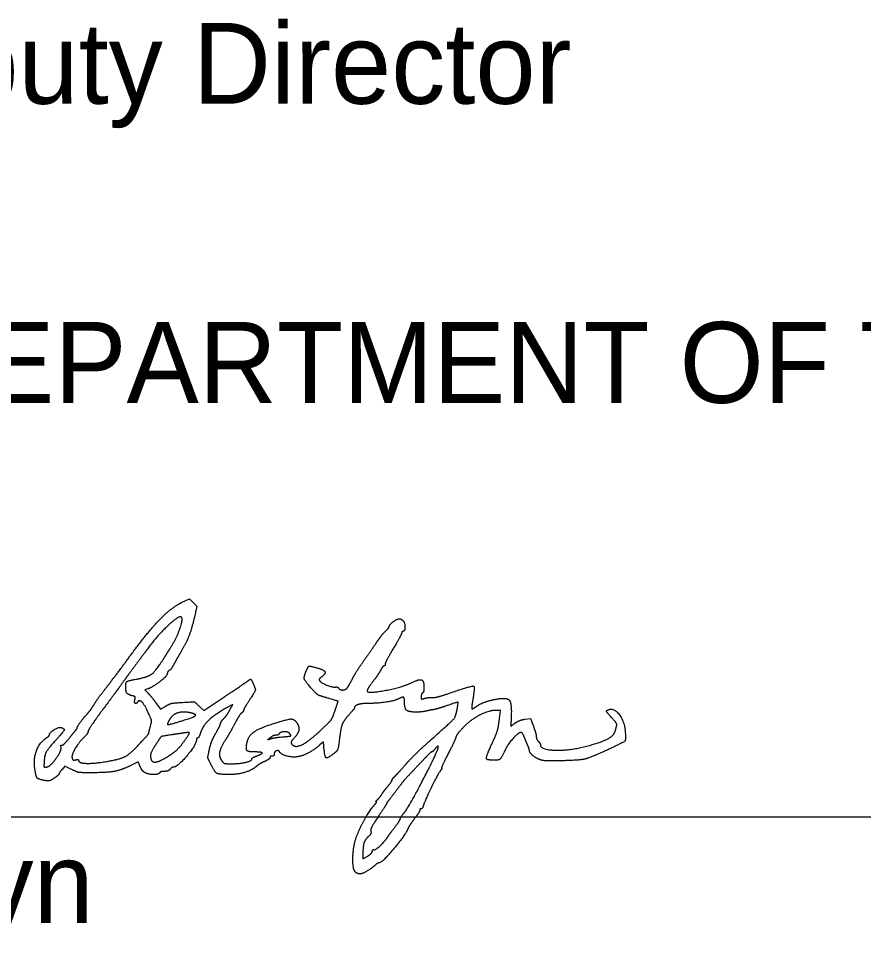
# Model space of a CAD drawing. Extents: x -7.5 to 26.5, y 3.5 to 25.5.
# Drawn here: x 18.323 to 19.785, y 10.747 to 12.355 of the extents above; entities that cross this region are included whole.
import ezdxf

# ---------------------------------------------------------------- set-up
doc = ezdxf.new("R2010")
doc.units = 0
doc.layers.add('SH_Data', color=7, linetype='Continuous')
doc.layers.add('SH_Text', color=7, linetype='Continuous')

msp = doc.modelspace()

# ---------------------------------------------------------------- linework, layer by layer
at = {"layer": 'SH_Data'}
msp.add_line((17.0432, 10.9729), (20.5432, 10.9729), dxfattribs=at)
at = {"layer": 'SH_Text'}
for points in [[(18.6062, 11.3442), (18.6188, 11.35), (18.6252, 11.3436), (18.6316, 11.3373), (18.6272, 11.3186)], [(18.5463, 11.1942), (18.5413, 11.1926), (18.5464, 11.1875)], [(18.6353, 11.1645), (18.6434, 11.1569), (18.6796, 11.181)], [(18.5601, 11.1708), (18.5687, 11.1593), (18.5775, 11.1645)], [(18.6891, 11.1592), (18.6936, 11.1672), (18.6881, 11.1642)], [(19.155, 11.1433), (19.1565, 11.1571), (19.1487, 11.1571)], [(19.1988, 11.1417), (19.2085, 11.1432), (19.2136, 11.1297)], [(18.8509, 11.0955), (18.8503, 11.1024), (18.8444, 11.0972)], [(18.5333, 11.0599), (18.5299, 11.068), (18.5161, 11.0611)], [(18.4146, 11.0549), (18.4031, 11.0607), (18.3981, 11.0549)], [(18.9187, 10.9094), (18.9187, 10.9), (18.9262, 10.9044)]]:
    msp.add_lwpolyline(points, dxfattribs=at)
for points in [[(18.5167, 11.2523), (18.5463, 11.2929), (18.5881, 11.3358), (18.6062, 11.3442)], [(18.6048, 11.3184), (18.6011, 11.322), (18.5626, 11.2863), (18.5472, 11.265)], [(18.5865, 11.2663), (18.5959, 11.2812), (18.6079, 11.3153), (18.6048, 11.3184)], [(18.6272, 11.3186), (18.6222, 11.2974), (18.613, 11.2738), (18.6036, 11.2579)], [(18.9643, 11.3022), (18.9643, 11.3051), (18.9775, 11.3154), (18.9812, 11.3154)], [(18.9812, 11.3154), (18.9832, 11.3155), (18.9862, 11.3142), (18.9878, 11.3126)], [(18.9878, 11.3126), (18.9913, 11.3092), (18.9916, 11.2939), (18.9883, 11.2939)], [(18.9439, 11.2769), (18.9478, 11.2828), (18.954, 11.2905), (18.9577, 11.2941)], [(18.9577, 11.2941), (18.9613, 11.2978), (18.9643, 11.3014), (18.9643, 11.3022)], [(18.9859, 11.2914), (18.9859, 11.29), (18.9794, 11.2779), (18.9715, 11.2645)], [(18.9883, 11.2939), (18.9869, 11.2939), (18.9859, 11.2928), (18.9859, 11.2914)], [(18.9223, 11.2459), (18.9302, 11.2571), (18.9399, 11.2711), (18.9439, 11.2769)], [(18.5472, 11.265), (18.5436, 11.26), (18.5342, 11.2474), (18.5263, 11.2369)], [(18.5759, 11.2496), (18.5792, 11.2548), (18.584, 11.2623), (18.5865, 11.2663)], [(18.6036, 11.2579), (18.6001, 11.252), (18.5949, 11.2428), (18.592, 11.2375)], [(18.9715, 11.2645), (18.9635, 11.2511), (18.9571, 11.2388), (18.9571, 11.237)], [(18.4765, 11.1988), (18.4854, 11.2102), (18.5035, 11.2342), (18.5167, 11.2523)], [(18.5261, 11.211), (18.5467, 11.2147), (18.5608, 11.2256), (18.5759, 11.2496)], [(18.9009, 11.2123), (18.9047, 11.2196), (18.9143, 11.2347), (18.9223, 11.2459)], [(18.5263, 11.2369), (18.5183, 11.2264), (18.5102, 11.2154), (18.5083, 11.2124)], [(18.5835, 11.226), (18.5817, 11.2249), (18.5803, 11.2225), (18.5803, 11.2206)], [(18.592, 11.2375), (18.5892, 11.2322), (18.5854, 11.227), (18.5835, 11.226)], [(18.83, 11.1947), (18.8185, 11.2078), (18.8162, 11.2146), (18.8202, 11.2242)], [(18.8202, 11.2242), (18.8239, 11.2332), (18.8271, 11.2342), (18.8398, 11.2305)], [(18.8398, 11.2305), (18.8518, 11.2269), (18.8546, 11.2207), (18.847, 11.2149)], [(18.9498, 11.2273), (18.948, 11.2237), (18.9419, 11.2146), (18.9362, 11.2071)], [(18.9551, 11.2339), (18.954, 11.2339), (18.9516, 11.2309), (18.9498, 11.2273)], [(18.9571, 11.237), (18.9571, 11.2353), (18.9562, 11.2339), (18.9551, 11.2339)], [(18.5083, 11.2124), (18.5063, 11.2095), (18.4909, 11.1885), (18.4741, 11.1659)], [(18.5083, 11.1989), (18.5083, 11.2057), (18.5124, 11.2085), (18.5261, 11.211)], [(18.5803, 11.2206), (18.5803, 11.2168), (18.5545, 11.1968), (18.5463, 11.1942)], [(18.6796, 11.181), (18.6996, 11.1942), (18.7172, 11.2062), (18.7188, 11.2075)], [(18.7188, 11.2075), (18.7233, 11.2113), (18.7257, 11.2104), (18.7287, 11.2038)], [(18.847, 11.2149), (18.8442, 11.2128), (18.8428, 11.21), (18.8437, 11.2086)], [(18.8437, 11.2086), (18.8464, 11.2049), (18.8663, 11.1967), (18.8709, 11.1974)], [(18.8916, 11.1961), (18.8929, 11.1978), (18.8971, 11.205), (18.9009, 11.2123)], [(18.9362, 11.2071), (18.9305, 11.1996), (18.9259, 11.1924), (18.9259, 11.191)], [(19.0034, 11.2053), (19.0164, 11.2115), (19.0243, 11.2083), (19.0243, 11.1969)], [(18.455, 11.1695), (18.4579, 11.1743), (18.4676, 11.1875), (18.4765, 11.1988)], [(18.5192, 11.1825), (18.5121, 11.1843), (18.5083, 11.19), (18.5083, 11.1989)], [(18.7287, 11.2038), (18.7331, 11.1942), (18.7321, 11.1901), (18.7219, 11.1742)], [(18.8535, 11.1796), (18.8427, 11.1827), (18.8378, 11.1859), (18.83, 11.1947)], [(18.8709, 11.1974), (18.8732, 11.1978), (18.8757, 11.197), (18.8766, 11.1956)], [(18.8766, 11.1956), (18.8787, 11.1921), (18.8888, 11.1925), (18.8916, 11.1961)], [(18.9259, 11.191), (18.9259, 11.1858), (18.9855, 11.1967), (19.0034, 11.2053)], [(19.0243, 11.1969), (19.0243, 11.1923), (19.0232, 11.1879), (19.0219, 11.1871)], [(19.0666, 11.1862), (19.107, 11.2001), (19.1129, 11.1984), (19.1087, 11.1746)], [(18.5243, 11.1762), (18.5253, 11.1798), (18.524, 11.1813), (18.5192, 11.1825)], [(18.5286, 11.1714), (18.5262, 11.1675), (18.523, 11.1711), (18.5243, 11.1762)], [(18.5464, 11.1875), (18.5493, 11.1846), (18.5554, 11.1771), (18.5601, 11.1708)], [(18.8702, 11.1558), (18.8759, 11.1727), (18.8755, 11.1732), (18.8535, 11.1796)], [(18.9792, 11.1765), (18.9736, 11.1735), (18.9435, 11.1691), (18.9285, 11.1691)], [(18.9907, 11.1718), (18.9907, 11.1791), (18.987, 11.1806), (18.9792, 11.1765)], [(19.0219, 11.1871), (19.0205, 11.1863), (19.0195, 11.1835), (19.0195, 11.1808)], [(19.0195, 11.1808), (19.0195, 11.1769), (19.0205, 11.1763), (19.0249, 11.1777)], [(19.0249, 11.1777), (19.0278, 11.1787), (19.0337, 11.1793), (19.0378, 11.1792)], [(19.0378, 11.1792), (19.042, 11.179), (19.0549, 11.1822), (19.0666, 11.1862)], [(19.1147, 11.1637), (19.122, 11.1688), (19.1402, 11.1751), (19.1539, 11.1772)], [(19.1539, 11.1772), (19.1685, 11.1795), (19.1762, 11.1691), (19.1754, 11.1479)], [(18.4387, 11.1476), (18.4452, 11.1549), (18.4495, 11.1606), (18.455, 11.1695)], [(18.4741, 11.1659), (18.4573, 11.1432), (18.4435, 11.1231), (18.4435, 11.1211)], [(18.5474, 11.1528), (18.5413, 11.1665), (18.5315, 11.1762), (18.5286, 11.1714)], [(18.5775, 11.1645), (18.584, 11.1684), (18.5915, 11.17), (18.6067, 11.1709)], [(18.6067, 11.1709), (18.627, 11.1721), (18.6272, 11.1721), (18.6353, 11.1645)], [(18.6881, 11.1642), (18.6647, 11.1517), (18.6419, 11.131), (18.6378, 11.1185)], [(18.6764, 11.1411), (18.6818, 11.1471), (18.6843, 11.1506), (18.6891, 11.1592)], [(18.7219, 11.1742), (18.7166, 11.166), (18.7123, 11.1584), (18.7123, 11.1573)], [(18.9043, 11.1619), (18.9043, 11.161), (18.9001, 11.1556), (18.8949, 11.1499)], [(18.9285, 11.1691), (18.917, 11.1691), (18.9043, 11.1653), (18.9043, 11.1619)], [(19.01, 11.1541), (18.9976, 11.1542), (18.9907, 11.1605), (18.9907, 11.1718)], [(19.037, 11.1066), (19.0725, 11.1381), (19.0794, 11.1463), (19.0819, 11.1596)], [(19.0612, 11.1642), (19.0534, 11.1615), (19.0438, 11.1588), (19.0399, 11.1581)], [(19.0819, 11.1596), (19.084, 11.1711), (19.0822, 11.1715), (19.0612, 11.1642)], [(19.1087, 11.1746), (19.1074, 11.1669), (19.1067, 11.1603), (19.1072, 11.1598)], [(19.1072, 11.1598), (19.1076, 11.1594), (19.111, 11.1611), (19.1147, 11.1637)], [(19.3455, 11.1485), (19.3402, 11.1542), (19.3399, 11.1568), (19.3445, 11.1586)], [(19.3445, 11.1586), (19.3531, 11.1619), (19.3716, 11.137), (19.3726, 11.1207)], [(18.4243, 11.1271), (18.4243, 11.1287), (18.4334, 11.1417), (18.4387, 11.1476)], [(18.5507, 11.1283), (18.5533, 11.1381), (18.553, 11.1403), (18.5474, 11.1528)], [(18.5859, 11.1437), (18.5789, 11.133), (18.5834, 11.1321), (18.6079, 11.1397)], [(18.6185, 11.1532), (18.6076, 11.1554), (18.5902, 11.1503), (18.5859, 11.1437)], [(18.6079, 11.1397), (18.6271, 11.1456), (18.6311, 11.1507), (18.6185, 11.1532)], [(18.7018, 11.1431), (18.6937, 11.1276), (18.6859, 11.1139), (18.6798, 11.1042)], [(18.7087, 11.1524), (18.7068, 11.1507), (18.7037, 11.1465), (18.7018, 11.1431)], [(18.7123, 11.1573), (18.7123, 11.1562), (18.7107, 11.154), (18.7087, 11.1524)], [(18.8519, 11.1285), (18.8624, 11.1386), (18.8665, 11.1447), (18.8702, 11.1558)], [(18.8949, 11.1499), (18.8864, 11.1404), (18.8807, 11.1279), (18.8791, 11.1151)], [(19.0267, 11.1555), (19.0234, 11.1548), (19.0159, 11.1541), (19.01, 11.1541)], [(19.0399, 11.1581), (19.0359, 11.1575), (19.03, 11.1563), (19.0267, 11.1555)], [(19.1487, 11.1571), (19.136, 11.1571), (19.1022, 11.1387), (19.09, 11.1251)], [(19.1403, 11.0955), (19.1494, 11.1154), (19.1534, 11.1285), (19.155, 11.1433)], [(19.1754, 11.1479), (19.1747, 11.1295), (19.1746, 11.1297), (19.1823, 11.1353)], [(19.3546, 11.1194), (19.3585, 11.1312), (19.357, 11.1361), (19.3455, 11.1485)], [(18.3763, 11.1151), (18.3763, 11.1188), (18.3931, 11.1288), (18.3969, 11.1274)], [(18.3969, 11.1274), (18.4028, 11.1251), (18.4006, 11.1202), (18.3862, 11.1043)], [(18.4219, 11.1228), (18.4232, 11.1244), (18.4243, 11.1263), (18.4243, 11.1271)], [(18.5311, 11.0978), (18.5471, 11.1154), (18.5475, 11.1159), (18.5507, 11.1283)], [(18.6639, 11.117), (18.6683, 11.1246), (18.6721, 11.1323), (18.6724, 11.1341)], [(18.6724, 11.1341), (18.6726, 11.1358), (18.6744, 11.139), (18.6764, 11.1411)], [(18.718, 11.1003), (18.7201, 11.1116), (18.7363, 11.1249), (18.7556, 11.1314)], [(18.7556, 11.1314), (18.7875, 11.142), (18.8009, 11.1424), (18.806, 11.1329)], [(18.7949, 11.0997), (18.8003, 11.091), (18.827, 11.1045), (18.8519, 11.1285)], [(18.806, 11.1329), (18.8092, 11.1269), (18.8058, 11.1155), (18.7984, 11.1076)], [(19.1823, 11.1353), (19.1861, 11.1379), (19.1935, 11.1408), (19.1988, 11.1417)], [(19.2136, 11.1297), (19.2164, 11.1222), (19.2187, 11.1141), (19.2187, 11.1116)], [(18.3716, 11.1098), (18.3742, 11.1114), (18.3763, 11.1138), (18.3763, 11.1151)], [(18.4097, 11.1079), (18.4151, 11.1145), (18.4205, 11.1212), (18.4219, 11.1228)], [(18.4361, 11.1104), (18.4262, 11.1007), (18.4139, 11.0786), (18.4157, 11.074)], [(18.4435, 11.1211), (18.4434, 11.1191), (18.4401, 11.1143), (18.4361, 11.1104)], [(18.5887, 11.1149), (18.5709, 11.1123), (18.5688, 11.1112), (18.5616, 11.0999)], [(18.6061, 11.1175), (18.6004, 11.1166), (18.5926, 11.1155), (18.5887, 11.1149)], [(18.611, 11.1059), (18.6189, 11.1172), (18.6179, 11.1194), (18.6061, 11.1175)], [(18.6378, 11.1185), (18.6361, 11.1134), (18.6338, 11.1091), (18.6327, 11.1091)], [(18.653, 11.0891), (18.6546, 11.0968), (18.6595, 11.1094), (18.6639, 11.117)], [(18.7678, 11.1139), (18.7655, 11.1139), (18.7615, 11.1122), (18.7589, 11.1101)], [(18.7591, 11.108), (18.7617, 11.1089), (18.7693, 11.1102), (18.7759, 11.1108)], [(18.7733, 11.116), (18.7726, 11.1149), (18.7701, 11.1139), (18.7678, 11.1139)], [(18.7918, 11.1171), (18.789, 11.1205), (18.7756, 11.1197), (18.7733, 11.116)], [(18.7759, 11.1108), (18.7926, 11.1123), (18.795, 11.1133), (18.7918, 11.1171)], [(18.8791, 11.1151), (18.8763, 11.0926), (18.8745, 11.0871), (18.8689, 11.0827)], [(19.0795, 11.1105), (19.0795, 11.109), (19.0735, 11.0961), (19.0662, 11.082)], [(19.09, 11.1251), (19.0842, 11.1187), (19.0795, 11.1121), (19.0795, 11.1105)], [(19.1919, 11.1187), (19.1876, 11.1187), (19.1693, 11.0982), (19.1646, 11.088)], [(19.1974, 11.1121), (19.196, 11.1157), (19.1935, 11.1187), (19.1919, 11.1187)], [(19.2034, 11.0979), (19.2016, 11.1021), (19.1989, 11.1085), (19.1974, 11.1121)], [(19.2187, 11.1116), (19.2187, 11.1091), (19.2203, 11.1054), (19.2223, 11.1035)], [(19.3057, 11.0951), (19.3294, 11.1013), (19.3523, 11.1127), (19.3546, 11.1194)], [(19.3726, 11.1207), (19.3735, 11.1054), (19.3708, 11.1022), (19.3474, 11.0913)], [(18.3514, 11.0535), (18.3484, 11.072), (18.3592, 11.102), (18.3716, 11.1098)], [(18.3862, 11.1043), (18.3726, 11.0891), (18.3676, 11.079), (18.367, 11.0651)], [(18.3963, 11.0937), (18.3955, 11.0957), (18.396, 11.097), (18.3974, 11.0966)], [(18.3974, 11.0966), (18.3989, 11.0962), (18.4044, 11.1013), (18.4097, 11.1079)], [(18.4746, 11.0685), (18.4973, 11.0721), (18.5169, 11.0823), (18.5311, 11.0978)], [(18.5616, 11.0999), (18.5534, 11.0873), (18.5502, 11.0775), (18.5524, 11.0717)], [(18.5812, 11.0772), (18.5923, 11.0842), (18.6033, 11.0947), (18.611, 11.1059)], [(18.6306, 11.1061), (18.6305, 11.0976), (18.5974, 11.0587), (18.5903, 11.0587)], [(18.6327, 11.1091), (18.6316, 11.1091), (18.6306, 11.1078), (18.6306, 11.1061)], [(18.6798, 11.1042), (18.6718, 11.0916), (18.6696, 11.0763), (18.6747, 11.0695)], [(18.7316, 11.0851), (18.7201, 11.0851), (18.716, 11.0897), (18.718, 11.1003)], [(18.7589, 11.1101), (18.7543, 11.1064), (18.7543, 11.1063), (18.7591, 11.108)], [(18.7984, 11.1076), (18.7956, 11.1047), (18.7941, 11.1011), (18.7949, 11.0997)], [(18.8444, 11.0972), (18.835, 11.0891), (18.815, 11.0784), (18.8059, 11.0768)], [(18.8689, 11.0827), (18.8571, 11.0734), (18.8527, 11.0766), (18.8509, 11.0955)], [(18.9904, 10.98), (18.998, 10.9887), (19.0513, 11.0925), (19.0492, 11.0946)], [(18.993, 11.0638), (19.0002, 11.0722), (19.02, 11.0915), (19.037, 11.1066)], [(19.0492, 11.0946), (19.0484, 11.0953), (19.0459, 11.0935), (19.0435, 11.0905)], [(19.1477, 11.0707), (19.1332, 11.0707), (19.1315, 11.0761), (19.1403, 11.0955)], [(19.2067, 11.0883), (19.2067, 11.0895), (19.2052, 11.0938), (19.2034, 11.0979)], [(19.2223, 11.1035), (19.2242, 11.1015), (19.2259, 11.0988), (19.2259, 11.0975)], [(19.2259, 11.0975), (19.2259, 11.0889), (19.2765, 11.0874), (19.3057, 11.0951)], [(18.3718, 11.0591), (18.3781, 11.0601), (18.3982, 11.0885), (18.3963, 11.0937)], [(18.655, 11.0651), (18.6505, 11.0742), (18.6504, 11.0765), (18.653, 11.0891)], [(18.7267, 11.0733), (18.7267, 11.0744), (18.7304, 11.0765), (18.7349, 11.0782)], [(18.7349, 11.0782), (18.7452, 11.0819), (18.7437, 11.0851), (18.7316, 11.0851)], [(18.7651, 11.0813), (18.7651, 11.0794), (18.7634, 11.0779), (18.7615, 11.0779)], [(18.7746, 11.0853), (18.7725, 11.0886), (18.7651, 11.0854), (18.7651, 11.0813)], [(18.8059, 11.0768), (18.7973, 11.0752), (18.7775, 11.0806), (18.7746, 11.0853)], [(19.0377, 11.0851), (19.0369, 11.0851), (19.033, 11.0816), (19.0289, 11.0773)], [(19.0435, 11.0905), (19.0411, 11.0875), (19.0385, 11.0851), (19.0377, 11.0851)], [(19.0662, 11.082), (19.059, 11.0679), (19.0538, 11.0563), (19.0548, 11.0563)], [(19.1646, 11.088), (19.1588, 11.0756), (19.154, 11.0707), (19.1477, 11.0707)], [(19.2224, 11.0728), (19.2153, 11.0761), (19.2069, 11.0845), (19.2067, 11.0883)], [(19.3474, 11.0913), (19.3126, 11.0749), (19.2916, 11.0702), (19.2523, 11.0697)], [(18.367, 11.0651), (18.3667, 11.0595), (18.3676, 11.0585), (18.3718, 11.0591)], [(18.4157, 11.074), (18.4166, 11.0716), (18.4189, 11.0706), (18.4219, 11.0714)], [(18.4219, 11.0714), (18.4245, 11.0721), (18.4267, 11.0718), (18.4267, 11.0707)], [(18.4267, 11.0707), (18.4267, 11.066), (18.4523, 11.0648), (18.4746, 11.0685)], [(18.5524, 11.0717), (18.5544, 11.0664), (18.568, 11.069), (18.5812, 11.0772)], [(18.6867, 11.046), (18.6692, 11.0461), (18.6622, 11.0503), (18.655, 11.0651)], [(18.6747, 11.0695), (18.6775, 11.0657), (18.6811, 11.0647), (18.6923, 11.0647)], [(18.6923, 11.0647), (18.7062, 11.0647), (18.7267, 11.0698), (18.7267, 11.0733)], [(18.7525, 11.0705), (18.7451, 11.0672), (18.7375, 11.0627), (18.7333, 11.0592)], [(18.7579, 11.0754), (18.7579, 11.0741), (18.7554, 11.0719), (18.7525, 11.0705)], [(18.7615, 11.0779), (18.7595, 11.0779), (18.7579, 11.0768), (18.7579, 11.0754)], [(18.9745, 11.0434), (18.9774, 11.0463), (18.9858, 11.0555), (18.993, 11.0638)], [(19.0289, 11.0773), (19.0248, 11.073), (19.0143, 11.0619), (19.0055, 11.0527)], [(19.2523, 11.0697), (19.2373, 11.0695), (19.227, 11.0706), (19.2224, 11.0728)], [(18.368, 11.0357), (18.3571, 11.0378), (18.3533, 11.0419), (18.3514, 11.0535)], [(18.393, 11.0473), (18.393, 11.0463), (18.3893, 11.043), (18.3847, 11.0398)], [(18.3981, 11.0549), (18.3953, 11.0517), (18.3931, 11.0483), (18.393, 11.0473)], [(18.4454, 11.0491), (18.4299, 11.0491), (18.424, 11.0502), (18.4146, 11.0549)], [(18.5161, 11.0611), (18.5005, 11.0534), (18.4753, 11.0491), (18.4454, 11.0491)], [(18.5415, 11.0493), (18.5388, 11.0507), (18.5351, 11.0555), (18.5333, 11.0599)], [(18.5671, 11.0491), (18.5651, 11.0459), (18.5476, 11.046), (18.5415, 11.0493)], [(18.5753, 11.0515), (18.5716, 11.0515), (18.5679, 11.0504), (18.5671, 11.0491)], [(18.5851, 11.0551), (18.5834, 11.0531), (18.579, 11.0515), (18.5753, 11.0515)], [(18.5903, 11.0587), (18.589, 11.0587), (18.5867, 11.0571), (18.5851, 11.0551)], [(18.7333, 11.0592), (18.7256, 11.0528), (18.7012, 11.0459), (18.6867, 11.046)], [(19.0055, 11.0527), (18.9967, 11.0434), (18.9868, 11.0322), (18.9835, 11.0277)], [(19.0541, 11.0545), (19.0514, 11.0526), (19.0262, 11.0016), (19.0232, 10.9921)], [(19.0548, 11.0563), (19.0558, 11.0563), (19.0555, 11.0554), (19.0541, 11.0545)], [(18.3847, 11.0398), (18.3782, 11.0354), (18.3745, 11.0345), (18.368, 11.0357)], [(18.9625, 11.0264), (18.9661, 11.0307), (18.9691, 11.0351), (18.9691, 11.0362)], [(18.9691, 11.0362), (18.9691, 11.0374), (18.9716, 11.0406), (18.9745, 11.0434)], [(18.9523, 11.0131), (18.9542, 11.0162), (18.9588, 11.0221), (18.9625, 11.0264)], [(18.9835, 11.0277), (18.9754, 11.0168), (18.9649, 11.003), (18.9619, 10.9994)], [(18.9386, 10.9933), (18.9413, 10.9963), (18.9428, 10.9987), (18.9419, 10.9987)], [(18.9419, 10.9987), (18.941, 10.9987), (18.9421, 11.0007), (18.9445, 11.0031)], [(18.9445, 11.0031), (18.9468, 11.0055), (18.9503, 11.01), (18.9523, 11.0131)], [(18.9619, 10.9994), (18.9606, 10.9978), (18.9595, 10.9961), (18.9595, 10.9955)], [(18.9085, 10.9407), (18.9144, 10.9555), (18.9315, 10.9854), (18.9386, 10.9933)], [(18.9595, 10.9955), (18.9595, 10.995), (18.9531, 10.985), (18.9454, 10.9734)], [(19.0171, 10.9842), (19.0171, 10.9828), (19.0128, 10.9761), (19.0076, 10.9692)], [(19.0193, 10.9867), (19.0181, 10.9867), (19.0171, 10.9856), (19.0171, 10.9842)], [(19.0232, 10.9921), (19.0223, 10.9891), (19.0205, 10.9867), (19.0193, 10.9867)], [(18.9454, 10.9734), (18.9367, 10.9604), (18.9318, 10.9506), (18.9325, 10.9479)], [(18.9733, 10.9539), (18.9789, 10.9613), (18.9835, 10.9684), (18.9835, 10.9697)], [(18.9835, 10.9697), (18.9835, 10.9711), (18.9866, 10.9757), (18.9904, 10.98)], [(19.0076, 10.9692), (19.0024, 10.9623), (18.9972, 10.9543), (18.9962, 10.9514)], [(18.9962, 10.9514), (18.9925, 10.9416), (18.9514, 10.8931), (18.9467, 10.8931)], [(18.9607, 10.9366), (18.962, 10.9388), (18.9676, 10.9465), (18.9733, 10.9539)], [(18.9067, 10.8763), (18.9007, 10.88), (18.902, 10.9243), (18.9085, 10.9407)], [(18.9288, 10.9393), (18.9228, 10.9341), (18.9187, 10.9218), (18.9187, 10.9094)], [(18.9325, 10.9479), (18.9331, 10.9454), (18.9316, 10.9417), (18.9288, 10.9393)], [(18.9379, 10.9159), (18.9398, 10.9147), (18.9564, 10.9299), (18.9607, 10.9366)], [(18.9262, 10.9044), (18.9303, 10.9068), (18.9342, 10.9106), (18.9349, 10.9129)], [(18.9349, 10.9129), (18.9355, 10.9152), (18.9368, 10.9165), (18.9379, 10.9159)], [(18.9392, 10.8885), (18.933, 10.8828), (18.9171, 10.8739), (18.9132, 10.8739)], [(18.9467, 10.8931), (18.9453, 10.8931), (18.9419, 10.8911), (18.9392, 10.8885)], [(18.9132, 10.8739), (18.9116, 10.874), (18.9086, 10.875), (18.9067, 10.8763)]]:
    msp.add_open_spline(points, degree=2, dxfattribs=at)

# ---------------------------------------------------------------- texts
for s, p in [('District       Deputy Director', (17.0432, 12.2071)), ('DIRECTOR, DEPARTMENT OF TRANSPORTATION', (17.0432, 11.6894)), ('Pamela Boratyn', (17.121, 10.789))]:
    msp.add_text(s, height=0.14, dxfattribs=at).set_placement(p)

doc.saveas('drawing.dxf')
